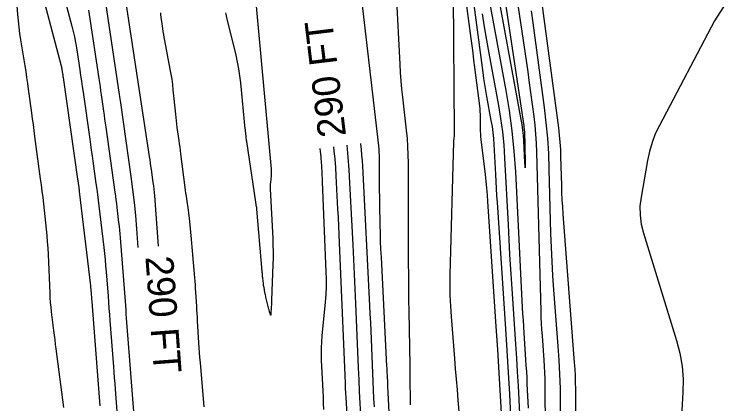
# Model space of a CAD drawing. Extents: x 1768942 to 1774819, y 723037 to 732099.
# Drawn here: x 1770736.7 to 1770890.7, y 725835.9 to 725920.2 of the extents above; entities that cross this region are included whole.
import ezdxf

# ---------------------------------------------------------------- set-up
doc = ezdxf.new("R2010")
doc.units = 0
doc.layers.add('R_Contour Annot', color=7, linetype='Continuous')
doc.layers.add('R_Contours', color=7, linetype='Continuous')

msp = doc.modelspace()

# ---------------------------------------------------------------- linework, layer by layer
at = {"layer": 'R_Contours'}
for points in [[(1770839.47, 725946.02), (1770846.98, 725896.03), (1770846.99, 725895.94), (1770847.01, 725895.84), (1770847.02, 725895.75), (1770847.03, 725895.66), (1770847.08, 725895.3), (1770847.09, 725895.21), (1770847.1, 725895.12), (1770847.1, 725895.03), (1770847.11, 725894.94), (1770847.29, 725888.11), (1770847.31, 725887.23), (1770847.3, 725886.94), (1770847.28, 725887.23), (1770847.23, 725888.11), (1770846.99, 725892.81), (1770846.91, 725893.98), (1770846.79, 725895.15), (1770846.64, 725896.31), (1770846.44, 725897.46), (1770838.39, 725941.14)], [(1770833.44, 725942.93), (1770838.12, 725907.6), (1770838.3, 725906.29), (1770838.5, 725904.99), (1770838.71, 725903.7), (1770838.94, 725902.4), (1770839.89, 725897.23), (1770840.11, 725895.93), (1770840.29, 725894.63), (1770840.42, 725893.32), (1770840.51, 725892.01), (1770840.84, 725885.53), (1770840.92, 725884.01), (1770841.01, 725882.5), (1770841.1, 725880.98), (1770841.2, 725879.46), (1770843.03, 725852.11), (1770843.33, 725847.4), (1770843.61, 725842.7), (1770843.88, 725838), (1770844.11, 725833.3)], [(1770851.88, 725800.69), (1770851.63, 725839.98), (1770851.61, 725841.31), (1770851.57, 725842.64), (1770851.5, 725843.98), (1770851.41, 725845.31), (1770851, 725850.63), (1770850.91, 725851.96), (1770850.83, 725853.3), (1770850.77, 725854.63), (1770850.73, 725855.96), (1770849.82, 725890.36), (1770849.74, 725892.3), (1770849.61, 725894.24), (1770849.44, 725896.18), (1770849.21, 725898.11), (1770848.18, 725905.84), (1770847.92, 725907.77), (1770847.66, 725909.7), (1770847.38, 725911.62), (1770847.09, 725913.55), (1770842.77, 725942.35)], [(1770842.2, 725832.62), (1770841.94, 725837.63), (1770841.67, 725842.63), (1770841.36, 725847.63), (1770841.04, 725852.62), (1770839.23, 725879.68), (1770839.12, 725881.14), (1770839, 725882.6), (1770838.85, 725884.07), (1770838.69, 725885.53), (1770837.79, 725893.08), (1770837.72, 725893.68), (1770837.68, 725894.29), (1770837.65, 725894.89), (1770837.63, 725895.5), (1770837.62, 725897.94), (1770837.6, 725898.54), (1770837.57, 725899.15), (1770837.52, 725899.75), (1770837.46, 725900.36), (1770836.41, 725908.66), (1770836.21, 725910.24), (1770836.01, 725911.82), (1770835.8, 725913.41), (1770835.59, 725914.99), (1770832.08, 725941.57)], [(1770822.47, 725835.7), (1770822.45, 725837.84), (1770822.43, 725839.98), (1770822.4, 725842.12), (1770822.37, 725844.26), (1770822.17, 725855.85), (1770822.13, 725858.49), (1770822.1, 725861.14), (1770822.08, 725863.79), (1770822.07, 725866.43), (1770822.03, 725887.97), (1770822, 725889.76), (1770821.92, 725891.55), (1770821.79, 725893.33), (1770821.61, 725895.11), (1770820.79, 725902.24), (1770820.6, 725904.02), (1770820.44, 725905.8), (1770820.3, 725907.59), (1770820.2, 725909.38), (1770818.66, 725939.74)], [(1770858.27, 725833.26), (1770858.23, 725839.04), (1770858.21, 725840.49), (1770858.16, 725841.94), (1770858.09, 725843.38), (1770857.99, 725844.82), (1770855.51, 725876.94), (1770855.4, 725878.5), (1770855.31, 725880.05), (1770855.24, 725881.61), (1770855.19, 725883.16), (1770855.03, 725889.4), (1770854.97, 725890.95), (1770854.86, 725892.51), (1770854.72, 725894.06), (1770854.54, 725895.6), (1770849.19, 725936.03)], [(1770747.44, 725835.06), (1770745.81, 725847.76), (1770745.68, 725848.76), (1770745.55, 725849.77), (1770745.42, 725850.77), (1770745.3, 725851.77), (1770744.8, 725855.78), (1770744.68, 725856.79), (1770744.59, 725857.79), (1770744.51, 725858.8), (1770744.46, 725859.81), (1770744.1, 725868.2), (1770744.03, 725869.57), (1770743.94, 725870.94), (1770743.82, 725872.31), (1770743.68, 725873.68), (1770743.09, 725879.15), (1770742.94, 725880.52), (1770742.78, 725881.89), (1770742.61, 725883.25), (1770742.43, 725884.62), (1770741.2, 725893.77), (1770741.02, 725895.05), (1770740.85, 725896.33), (1770740.68, 725897.6), (1770740.51, 725898.88), (1770739.82, 725903.98), (1770739.64, 725905.25), (1770739.46, 725906.53), (1770739.27, 725907.8), (1770739.06, 725909.07), (1770738.15, 725914.69), (1770737.95, 725916.06), (1770737.77, 725917.42), (1770737.62, 725918.79), (1770737.5, 725920.17), (1770736.71, 725930.34)], [(1770811.13, 725929.64), (1770815.52, 725891.69), (1770815.59, 725891.02), (1770815.63, 725890.35), (1770815.66, 725889.68), (1770815.67, 725889), (1770815.68, 725886.31), (1770815.68, 725885.64), (1770815.69, 725884.97), (1770815.7, 725884.29), (1770815.71, 725883.62), (1770815.86, 725874.56), (1770815.89, 725872.82), (1770815.94, 725871.09), (1770816.01, 725869.36), (1770816.09, 725867.62), (1770817.3, 725844.07), (1770817.32, 725843.58), (1770817.35, 725843.1), (1770817.37, 725842.62), (1770817.39, 725842.13), (1770817.47, 725840.2), (1770817.49, 725839.72), (1770817.51, 725839.23), (1770817.54, 725838.75), (1770817.56, 725838.27), (1770819.74, 725796.68)], [(1770741.59, 725929.05), (1770746.87, 725909.02), (1770746.92, 725908.82), (1770746.97, 725908.61), (1770747.01, 725908.41), (1770747.04, 725908.2), (1770747.17, 725907.37), (1770747.2, 725907.16), (1770747.23, 725906.95), (1770747.26, 725906.75), (1770747.29, 725906.54), (1770750.43, 725884.54), (1770750.46, 725884.31), (1770750.49, 725884.09), (1770750.52, 725883.86), (1770750.55, 725883.64), (1770750.68, 725882.74), (1770750.71, 725882.51), (1770750.74, 725882.29), (1770750.77, 725882.06), (1770750.8, 725881.83), (1770753.21, 725861.42), (1770753.25, 725861.06), (1770753.29, 725860.7), (1770753.32, 725860.33), (1770753.35, 725859.97), (1770753.47, 725858.51), (1770753.49, 725858.14), (1770753.52, 725857.78), (1770753.55, 725857.41), (1770753.58, 725857.05), (1770755.22, 725835.49)], [(1770746.11, 725929.34), (1770749.19, 725917.66), (1770749.49, 725916.48), (1770749.75, 725915.3), (1770749.98, 725914.12), (1770750.17, 725912.92), (1770750.89, 725908.14), (1770751.07, 725906.94), (1770751.25, 725905.75), (1770751.42, 725904.55), (1770751.6, 725903.35), (1770753.04, 725893.2), (1770753.22, 725892), (1770753.39, 725890.79), (1770753.56, 725889.59), (1770753.72, 725888.39), (1770754.4, 725883.58), (1770754.56, 725882.37), (1770754.72, 725881.17), (1770754.88, 725879.96), (1770755.02, 725878.76), (1770756.09, 725869.72), (1770756.24, 725868.41), (1770756.37, 725867.09), (1770756.5, 725865.78), (1770756.6, 725864.46), (1770757.01, 725859.19), (1770757.11, 725857.87), (1770757.21, 725856.55), (1770757.31, 725855.23), (1770757.41, 725853.92), (1770758.17, 725843.93), (1770758.27, 725842.72), (1770758.36, 725841.51), (1770758.45, 725840.29), (1770758.54, 725839.08), (1770758.98, 725833.28)], [(1770767.93, 725870.02), (1770767.11, 725880.91), (1770767.06, 725881.63), (1770766.98, 725882.34), (1770766.9, 725883.05), (1770766.81, 725883.76), (1770766.41, 725886.6), (1770766.31, 725887.3), (1770766.21, 725888.01), (1770766.1, 725888.72), (1770765.99, 725889.43), (1770759.93, 725929.4)], [(1770839.05, 725925.63), (1770843.09, 725903.72), (1770843.82, 725899.34), (1770844.41, 725894.95), (1770844.86, 725890.54), (1770845.16, 725886.11), (1770846.66, 725856.76), (1770846.74, 725855.37), (1770846.82, 725853.98), (1770846.9, 725852.59), (1770846.99, 725851.2), (1770847.37, 725845.49), (1770847.46, 725844.17), (1770847.54, 725842.86), (1770847.61, 725841.55), (1770847.68, 725840.23), (1770847.93, 725834.97)], [(1770831.71, 725924.16), (1770831.92, 725894.83), (1770831.92, 725894.76), (1770831.92, 725894.69), (1770831.92, 725894.62), (1770831.92, 725894.54), (1770831.91, 725894.25), (1770831.9, 725894.18), (1770831.9, 725894.11), (1770831.9, 725894.04), (1770831.89, 725893.97), (1770831.83, 725893.25), (1770831.82, 725893.11), (1770831.81, 725892.96), (1770831.8, 725892.82), (1770831.79, 725892.68), (1770831.01, 725863.84), (1770830.98, 725861.57), (1770831.01, 725859.3), (1770831.1, 725857.04), (1770831.25, 725854.77), (1770831.98, 725845.72), (1770832.16, 725843.46), (1770832.35, 725841.2), (1770832.54, 725838.94), (1770832.74, 725836.68), (1770835.63, 725804.22)], [(1770756.44, 725922.69), (1770759.45, 725902.83), (1770759.52, 725902.38), (1770759.59, 725901.93), (1770759.66, 725901.47), (1770759.72, 725901.02), (1770761.97, 725885.07), (1770762.34, 725882.26), (1770762.66, 725879.44), (1770762.94, 725876.62), (1770763.18, 725873.79), (1770763.48, 725869.69)], [(1770789.08, 725921.92), (1770792.3, 725886.65), (1770792.32, 725886.3), (1770792.33, 725885.94), (1770792.32, 725885.59), (1770792.29, 725885.23), (1770792.16, 725883.81), (1770792.13, 725883.46), (1770792.11, 725883.1), (1770792.11, 725882.74), (1770792.12, 725882.39), (1770792.66, 725871.66), (1770792.71, 725870.26), (1770792.73, 725868.86), (1770792.73, 725867.45), (1770792.69, 725866.05), (1770792.4, 725858.29), (1770792.39, 725857.95), (1770792.38, 725857.61), (1770792.36, 725857.27), (1770792.35, 725856.94), (1770792.26, 725855.21), (1770792.25, 725855.09), (1770792.23, 725855.05), (1770792.2, 725855.08), (1770792.16, 725855.19), (1770791.97, 725855.79), (1770791.93, 725855.94), (1770791.89, 725856.09), (1770791.85, 725856.24), (1770791.81, 725856.4), (1770791.19, 725858.96), (1770791.13, 725859.21), (1770791.07, 725859.47), (1770791.02, 725859.72), (1770790.97, 725859.97), (1770790.77, 725861.04), (1770790.73, 725861.27), (1770790.69, 725861.5), (1770790.66, 725861.73), (1770790.63, 725861.96), (1770790.5, 725863.1), (1770790.48, 725863.22), (1770790.47, 725863.33), (1770790.46, 725863.45), (1770790.45, 725863.57), (1770790.42, 725864.03), (1770790.41, 725864.15), (1770790.4, 725864.27), (1770790.39, 725864.38), (1770790.38, 725864.5), (1770789.24, 725878.03), (1770789.23, 725878.16), (1770789.21, 725878.29), (1770789.19, 725878.42), (1770789.17, 725878.55), (1770789.07, 725879.06), (1770789.05, 725879.19), (1770789.02, 725879.32), (1770789, 725879.44), (1770788.98, 725879.57), (1770787.03, 725892.67), (1770787, 725892.9), (1770786.97, 725893.13), (1770786.94, 725893.36), (1770786.91, 725893.59), (1770786.81, 725894.51), (1770786.78, 725894.74), (1770786.76, 725894.97), (1770786.74, 725895.2), (1770786.71, 725895.43), (1770785.72, 725905.36), (1770785.55, 725906.86), (1770785.32, 725908.36), (1770785.04, 725909.85), (1770784.71, 725911.33), (1770782.74, 725919.48), (1770782.66, 725919.83), (1770782.58, 725920.19), (1770782.51, 725920.54)], [(1770890.7, 725922.62), (1770888.24, 725918.79), (1770876.32, 725896.11), (1770875.45, 725894.3), (1770874.74, 725892.44), (1770874.17, 725890.53), (1770873.75, 725888.57), (1770872.36, 725880.63), (1770872.13, 725878.65), (1770872.14, 725876.69), (1770872.38, 725874.74), (1770872.86, 725872.81), (1770880.06, 725849.63), (1770880.78, 725846.85), (1770881.26, 725844.05), (1770881.47, 725841.21), (1770881.43, 725838.33), (1770880.76, 725826.79)], [(1770752.77, 725921.09), (1770752.92, 725920.17), (1770755.02, 725906.3), (1770755.15, 725905.42), (1770755.28, 725904.54), (1770755.41, 725903.66), (1770755.53, 725902.78), (1770756.03, 725899.26), (1770756.16, 725898.38), (1770756.28, 725897.5), (1770756.41, 725896.62), (1770756.53, 725895.74), (1770758.5, 725881.69), (1770758.61, 725880.87), (1770758.72, 725880.05), (1770758.82, 725879.23), (1770758.92, 725878.41), (1770759.31, 725875.14), (1770759.4, 725874.32), (1770759.49, 725873.5), (1770759.57, 725872.67), (1770759.63, 725871.85), (1770760.76, 725857.15), (1770760.84, 725856.24), (1770760.9, 725855.33), (1770760.97, 725854.42), (1770761.04, 725853.5), (1770761.32, 725849.86), (1770761.39, 725848.94), (1770761.46, 725848.03), (1770761.53, 725847.12), (1770761.6, 725846.21), (1770762.58, 725833.3)], [(1770768.34, 725920.5), (1770768.4, 725920.08), (1770768.8, 725917.09), (1770768.89, 725916.45), (1770768.99, 725915.82), (1770769.1, 725915.18), (1770769.21, 725914.55), (1770770.42, 725908.35), (1770770.62, 725907.24), (1770770.8, 725906.13), (1770770.95, 725905.01), (1770771.07, 725903.88), (1770771.59, 725898.56), (1770771.67, 725897.85), (1770771.75, 725897.14), (1770771.84, 725896.42), (1770771.93, 725895.71), (1770772.33, 725892.87), (1770772.43, 725892.16), (1770772.53, 725891.45), (1770772.62, 725890.74), (1770772.71, 725890.03), (1770773.65, 725882.69), (1770773.73, 725882.08), (1770773.81, 725881.47), (1770773.89, 725880.86), (1770773.98, 725880.25), (1770774.33, 725877.8), (1770774.41, 725877.19), (1770774.49, 725876.58), (1770774.56, 725875.97), (1770774.62, 725875.35), (1770775, 725871.52), (1770775.08, 725870.67), (1770775.16, 725869.83), (1770775.24, 725868.99), (1770775.31, 725868.14), (1770775.73, 725863.19), (1770775.79, 725862.41), (1770775.85, 725861.64), (1770775.9, 725860.86), (1770775.95, 725860.09), (1770776.13, 725856.98), (1770776.18, 725856.2), (1770776.22, 725855.43), (1770776.27, 725854.65), (1770776.32, 725853.88), (1770776.62, 725849.09), (1770776.69, 725848.03), (1770776.76, 725846.98), (1770776.84, 725845.92), (1770776.92, 725844.86), (1770777.71, 725835.23)], [(1770838, 725920.31), (1770838.43, 725917.47), (1770838.9, 725914.63), (1770839.4, 725911.8), (1770841.49, 725900.47), (1770841.97, 725897.64), (1770842.35, 725894.79), (1770842.64, 725891.93), (1770842.83, 725889.06), (1770843.57, 725874.61), (1770843.74, 725871.42), (1770843.92, 725868.24), (1770844.12, 725865.06), (1770844.33, 725861.87), (1770845.2, 725848.8), (1770845.4, 725845.79), (1770845.58, 725842.78), (1770845.74, 725839.77), (1770845.9, 725836.76), (1770846.48, 725824.73)], [(1770855.05, 725820.38), (1770854.95, 725836.18), (1770854.91, 725839.23), (1770854.81, 725842.29), (1770854.65, 725845.34), (1770854.45, 725848.39), (1770853.5, 725860.58), (1770853.29, 725863.63), (1770853.11, 725866.68), (1770852.97, 725869.73), (1770852.87, 725872.78), (1770852.51, 725886.7), (1770852.38, 725890.04), (1770852.16, 725893.37), (1770851.85, 725896.69), (1770851.45, 725900), (1770849.03, 725918.36), (1770848.68, 725920.96)], [(1770803.7, 725834.66), (1770803.66, 725835.99), (1770803.61, 725837.32), (1770803.56, 725838.65), (1770803.5, 725839.99), (1770803.23, 725845.31), (1770803.19, 725846.65), (1770803.2, 725847.98), (1770803.25, 725849.31), (1770803.36, 725850.63), (1770804.07, 725857.88), (1770804.2, 725859.53), (1770804.28, 725861.18), (1770804.29, 725862.84), (1770804.25, 725864.49), (1770803.44, 725883.9), (1770803.42, 725884.35), (1770803.4, 725884.8), (1770803.38, 725885.25), (1770803.35, 725885.7), (1770803.26, 725887.51), (1770803.23, 725887.96), (1770803.2, 725888.41), (1770803.16, 725888.86), (1770803.11, 725889.31), (1770802.89, 725891.13)], [(1770805.82, 725891.49), (1770805.91, 725890.65), (1770806.08, 725888.85), (1770806.22, 725887.04), (1770806.33, 725885.24), (1770806.7, 725877.99), (1770806.79, 725876.18), (1770806.88, 725874.37), (1770806.96, 725872.56), (1770807.04, 725870.75), (1770808.31, 725840.35), (1770808.36, 725839.28), (1770808.41, 725838.22), (1770808.46, 725837.16), (1770808.52, 725836.1), (1770808.74, 725831.85)], [(1770811.71, 725833.46), (1770811.58, 725836.01), (1770811.45, 725838.56), (1770811.34, 725841.11), (1770811.23, 725843.66), (1770810.64, 725857.61), (1770810.5, 725860.78), (1770810.36, 725863.95), (1770810.21, 725867.12), (1770810.05, 725870.29), (1770809.36, 725883.72), (1770809.19, 725886.51), (1770808.98, 725889.29), (1770808.74, 725891.84)], [(1770814.67, 725835.24), (1770814.57, 725837.07), (1770814.48, 725838.9), (1770814.4, 725840.72), (1770814.32, 725842.55), (1770814.01, 725849.87), (1770813.94, 725851.7), (1770813.85, 725853.52), (1770813.77, 725855.35), (1770813.67, 725857.18), (1770812.13, 725887.29), (1770812.06, 725888.51), (1770811.96, 725889.74), (1770811.85, 725890.96), (1770811.71, 725892.18), (1770811.71, 725892.2)]]:
    msp.add_lwpolyline(points, dxfattribs=at)

# ---------------------------------------------------------------- texts
at = {"layer": 'R_Contour Annot'}
for rotation, p in [(96.9193, (1770808.54, 725893.93)), (274.2297, (1770765.09, 725867.7))]:
    msp.add_text('290 FT', height=6, rotation=rotation, dxfattribs=at).set_placement(p)

doc.saveas('drawing.dxf')
